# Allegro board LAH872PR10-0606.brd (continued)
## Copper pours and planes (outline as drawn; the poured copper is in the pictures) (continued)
N17389450 on TOP (solid shape): 42.46,107.18 43.08,107.18 43.08,107.24 43.37,107.24 43.53,107.21 43.67,107.24 43.68,107.24 43.99,107.24 43.99,107.18 44.6,107.18 44.6,107.24 45.82,107.24 45.94,107.12 45.94,106.48 46.07,106.36 46.71,106.36 46.83,106.23 46.83,104.7 46.71,104.58 44.29,104.58 44.04,104.83 44.04,105.85 43.84,106.05 43.86,106.08 43.63,106.57 43.18,106.27 43.17,106.23 42.39,106.23 42.26,106.36 42.26,107.12 42.39,107.24 42.46,107.24
N17415515 on BOTTOM (solid shape): 78.49,147.06 78.56,147.03 78.59,146.97 78.94,146.63 79.3,146.97 79.33,147.03 79.4,147.06 80.52,147.06 80.52,147.01 80.87,146.66 81.23,147.01 81.23,147.06 82.58,147.06 83.51,146.14 83.51,143.37 83.37,143.23 76.74,143.23 76.33,143.64 76.33,144.73 76.31,144.76 75.8,144.76 75.79,144.76 75.79,145.01 75.79,145.01 76.34,145.01 76.34,145.02 76.34,145.56 76.34,145.56 75.79,145.56 75.79,145.56 75.79,145.81 75.79,145.82 76.33,145.82 76.34,145.82 76.34,145.91 76.36,145.91 76.36,146.87 76.55,147.06
N21380741 on BOTTOM (solid shape): 42.11,105.78 42.71,105.78 42.83,105.66 42.83,103.69 42.71,103.56 41.88,103.56 41.82,103.62 41.82,104.96 41.63,105.15 41.25,105.15 41.19,105.21 41.19,105.92 41.28,106.01 41.88,106.01
N23133643 on BOTTOM (solid shape): 189.35,56.74 189.35,55.6 188.06,54.3 188.06,53.79 187.92,53.65 187,53.65 186.9,53.75 186.9,55.48 187.37,55.95 188.07,55.95 188.25,56.13 188.25,56.88 188.43,57.06 189.04,57.06
N29179188 on TOP (solid shape): 184.18,66.16 184.18,65.58 183.98,65.38 182.7,65.38 182.03,64.7 182.03,63.05 181.9,62.92 180.44,62.92 180.1,62.59 178.93,62.59 178.82,62.7 178.82,63.74 178.83,63.8 178.82,63.86 178.82,65.62 178.96,65.77 179.92,65.77 180.17,65.51 180.55,65.51 180.72,65.68 180.72,66.12 180.76,66.16 183.1,66.16 183.3,66.35 183.99,66.35
N29179461 on TOP (solid shape): 185.26,64.45 185.26,60.13 184.88,59.75 183.49,59.75 183.49,60.51 183.3,60.7 182.91,60.7 182.72,60.51 182.72,59.75 182.15,59.75 182.03,59.88 182.03,61.4 182.53,61.91 182.53,64.64 182.66,64.77 184.95,64.77
N29179461 on BOTTOM (solid shape): 185.2,62.16 185.2,60.83 184.04,59.67 182.65,59.67 182.6,59.72 182.6,62.35 182.72,62.48 184.88,62.48
N33534280 on BOTTOM (solid shape): 111.1,44.45 111.92,44.45 111.98,44.38 111.98,43.87 110.97,43.87 110.46,44.38 110.46,44.83 110.71,44.83
N33564171 on BOTTOM (solid shape): 125,38.29 125,36.8 124.51,36.3 123.81,36.3 123.75,36.36 123.75,38.2 123.96,38.41 124.88,38.41

Small or netless copper shapes (teardrops, artwork), in the pictures only: 127 on TOP, 17 on BOTTOM, 2 on IN2

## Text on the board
Ref Des/Silkscreen Bottom: H8 | H12 | SPK | M2L4 | KB | BL | DCIN | TP | BATTERY | HDD | ODD | IO | FP | EDP | POWER | DIMM A | SODIMM-ONLY SUPPORT DDR4
User.Comments: LA-H872P | 2019-06-06 | 2020-06-06 | Monika | FDI52
Ref Des/Silkscreen Top: VGA
User.41: trace Width | Width/space | 8.3mil | 4mil | 5mil | 8.3 / 7 | 5.8 / 5.4 | 5 / 5.4 | 4 / 4 | 5 / 7.3 | 4 / 5.4 | 3.5 / 6.2 | 3.5 / 7.6 | L2/L5 | L2 | L5 | 10.5/4.5 | 7 / 5 | No REF | SB_1_0mm-6L(4mil & 5mil 50ohm)_181001 | L1-TOP | L2-VCC | L3-IN1 | L4-IN2 | L5-GND | L6-BOT | LAYER | NAME | STACKUP: 6 LAYER | 40 ohm | 50 ohm | THICKNESS=1.0mm | 72 ohm | 80 ohm | 85 ohm | 90 ohm | 100 ohm | Ref
User.42: FIGURE | SIZE | 8.0 | 22.0 | 28.0 | 35.0 | 118.0 | 126.0 | 130.0 | 154.0 | 31.0 | 43.0 | 47.0 | 63.0 | 220.0 | 55.0x24.0 | 63.0x24.0 | 63.0x35.0 | 71.0x31.0 | 102.0x31.0 | 157.0x118.0 | DRILL CHART: TOP to BOTTOM | ALL UNITS ARE IN MILS | TOLERANCE | +3.0/-3.0 | +2.0/-2.0 | PLATED | NON-PLATED | QTY | 3845 | 19 | 18 | 8 | 6 | 1 | 4 | 3 | 7
User.45: STACK-UP SETTING OK
